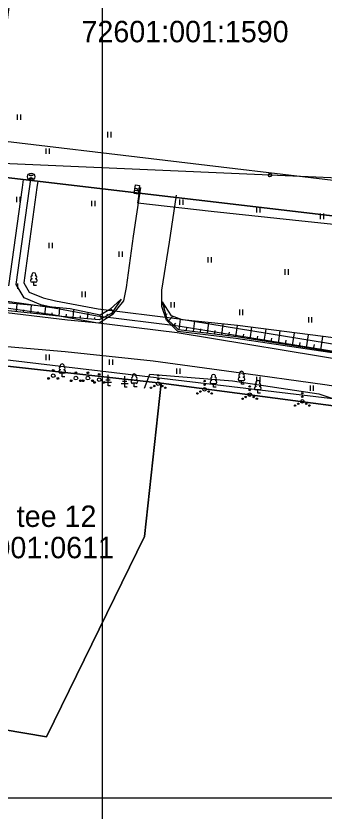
# Model space of a CAD drawing. Extents: x 532656 to 533339, y 6581345 to 6581629.
# Drawn here: x 533015 to 533058.1, y 6581419.8 to 6581531.1 of the extents above; entities that cross this region are included whole.
import ezdxf

# ---------------------------------------------------------------- set-up
doc = ezdxf.new("R2010")
doc.units = 0
for name, color, linetype in [('ELRAJATISMP', 7, 'Continuous'), ('HALJASTUS', 7, 'Continuous'), ('KASUTUSALA', 7, 'Continuous'), ('MPKAABEL', 7, 'Continuous'), ('MPOHULIIN', 7, 'Continuous'), ('PIIR', 7, 'Continuous'), ('POST', 7, 'Continuous'), ('PR_SIDE', 7, 'Continuous'), ('PUU', 7, 'Continuous'), ('RELJEEF', 7, 'Continuous'), ('TEE', 7, 'Continuous'), ('VORMISTUS', 7, 'Continuous'), ('VORMISTUS_1', 7, 'Continuous')]:
    doc.layers.add(name, color=color, linetype=linetype)

msp = doc.modelspace()

# ---------------------------------------------------------------- linework, layer by layer
at = {"layer": 'ELRAJATISMP'}
for p, q in [((533031.58, 6581506.72), (533032.17, 6581506.62)), ((533031.62, 6581506.99), (533032.21, 6581506.89))]:
    msp.add_line(p, q, dxfattribs=at)
msp.add_lwpolyline([(533031.51, 6581506.26), (533031.7, 6581507.44), (533032.29, 6581507.34), (533032.09, 6581506.17)], close=True, dxfattribs=at)
at = {"layer": 'HALJASTUS'}
for p, q in [((533015.17, 6581517.3), (533015.17, 6581516.54)), ((533015.63, 6581517.3), (533015.63, 6581516.54)), ((533027.79, 6581514.85), (533027.79, 6581514.09)), ((533028.24, 6581514.85), (533028.24, 6581514.09)), ((533019.18, 6581512.53), (533019.18, 6581511.77)), ((533019.64, 6581512.53), (533019.64, 6581511.77)), ((533015.05, 6581505.77), (533015.05, 6581505.01)), ((533015.5, 6581505.77), (533015.5, 6581505.01)), ((533025.55, 6581505.22), (533025.55, 6581504.46)), ((533026.01, 6581505.22), (533026.01, 6581504.46)), ((533037.89, 6581505.42), (533037.89, 6581504.66)), ((533038.35, 6581505.42), (533038.35, 6581504.66)), ((533048.65, 6581504.32), (533048.65, 6581503.56)), ((533049.11, 6581504.32), (533049.11, 6581503.56)), ((533057.56, 6581503.44), (533057.56, 6581502.67)), ((533058.01, 6581503.44), (533058.01, 6581502.67)), ((533019.6, 6581499.35), (533019.6, 6581498.59)), ((533020.06, 6581499.35), (533020.06, 6581498.59)), ((533029.39, 6581498.13), (533029.39, 6581497.37)), ((533029.85, 6581498.13), (533029.85, 6581497.37)), ((533041.86, 6581497.33), (533041.86, 6581496.57)), ((533042.31, 6581497.33), (533042.31, 6581496.57)), ((533052.64, 6581495.63), (533052.64, 6581494.87)), ((533053.1, 6581495.63), (533053.1, 6581494.87)), ((533015.21, 6581493.65), (533015.21, 6581492.89)), ((533024.2, 6581492.51), (533024.2, 6581491.75)), ((533024.66, 6581492.51), (533024.66, 6581491.75)), ((533036.67, 6581491.04), (533036.67, 6581490.28)), ((533037.12, 6581491.04), (533037.12, 6581490.28)), ((533046.25, 6581489.99), (533046.25, 6581489.23)), ((533046.7, 6581489.99), (533046.7, 6581489.23)), ((533055.91, 6581488.93), (533055.91, 6581488.17)), ((533056.37, 6581488.93), (533056.37, 6581488.17)), ((533019.18, 6581483.69), (533019.18, 6581482.93)), ((533019.63, 6581483.69), (533019.63, 6581482.93)), ((533028.04, 6581483.02), (533028.04, 6581482.25)), ((533028.49, 6581483.02), (533028.49, 6581482.25)), ((533037.45, 6581481.75), (533037.45, 6581480.99)), ((533037.9, 6581481.75), (533037.9, 6581480.99)), ((533048.64, 6581480.6), (533048.64, 6581479.84)), ((533049.1, 6581480.6), (533049.1, 6581479.84)), ((533056.15, 6581479.38), (533056.15, 6581478.62)), ((533056.6, 6581479.38), (533056.6, 6581478.62))]:
    msp.add_line(p, q, dxfattribs=at)
msp.add_lwpolyline([(533032.97, 6581478.99), (533033.72, 6581480.95), (533045.3, 6581480.01), (533057.4, 6581478.22), (533063.59, 6581476.17), (533064.85, 6581474.81)], dxfattribs=at)
for centre, radius in [((533034.89, 6581480.78), 0.1), ((533034.89, 6581480.28), 0.1), ((533041.38, 6581479.99), 0.1), ((533033.89, 6581479.05), 0.1), ((533034.33, 6581479.3), 0.1), ((533034.89, 6581479.63), 0.25), ((533035.46, 6581479.3), 0.1), ((533035.89, 6581479.05), 0.1), ((533041.38, 6581478.84), 0.25), ((533041.38, 6581479.49), 0.1), ((533047.7, 6581479.25), 0.1), ((533047.7, 6581478.75), 0.1), ((533040.38, 6581478.27), 0.1), ((533040.81, 6581478.52), 0.1), ((533041.94, 6581478.52), 0.1), ((533042.38, 6581478.27), 0.1), ((533047.14, 6581477.77), 0.1), ((533047.7, 6581478.1), 0.25), ((533048.27, 6581477.77), 0.1), ((533055.06, 6581478.3), 0.1), ((533055.06, 6581477.8), 0.1), ((533046.7, 6581477.52), 0.1), ((533048.7, 6581477.52), 0.1), ((533054.06, 6581476.57), 0.1), ((533054.49, 6581476.82), 0.1), ((533055.06, 6581477.15), 0.25), ((533055.62, 6581476.82), 0.1), ((533056.06, 6581476.57), 0.1)]:
    msp.add_circle(centre, radius, dxfattribs=at)
at = {"layer": 'KASUTUSALA'}
for points in [[(533013.98, 6581493.3), (533015.9, 6581507.09), (533016.05, 6581508.19), (533018.04, 6581507.96), (533017.92, 6581507.09), (533016.06, 6581493.72), (533016.82, 6581492.43), (533018.77, 6581491.63), (533020.53, 6581491.21), (533026.48, 6581490.1), (533037.85, 6581488.72), (533062.74, 6581484.63), (533088.6, 6581481.18), (533109.16, 6581472.91), (533120.73, 6581472.5), (533130.59, 6581473.14), (533152.46, 6581478.24)], [(533152.98, 6581476.31), (533130.88, 6581471.16), (533119.05, 6581470.39), (533116.99, 6581470.63), (533106.31, 6581471.91), (533088.09, 6581479.24), (533062.44, 6581482.66), (533037.57, 6581486.74), (533026.18, 6581488.12), (533021.07, 6581489.07), (533020.13, 6581489.24), (533009.66, 6581490.74)]]:
    msp.add_lwpolyline(points, dxfattribs=at)
at = {"layer": 'MPKAABEL'}
msp.add_lwpolyline([(533187.88, 6581502.84), (533186.34, 6581502.82), (533179.65, 6581502.93), (533170.99, 6581502.81), (533161.86, 6581502.74), (533157.45, 6581501.85), (533146.33, 6581499.15), (533143.65, 6581498.48), (533132.32, 6581495.71), (533125.95, 6581494.5), (533114.52, 6581495.45), (533102.79, 6581496.92), (533089.47, 6581498.82), (533077.24, 6581500), (533065.63, 6581501.23), (533053.69, 6581502.51), (533042.29, 6581503.73), (533032.02, 6581504.88), (533032.28, 6581506.42), (533031.89, 6581506.81)], dxfattribs=at)
msp.add_lwpolyline([(533187.88, 6581502.84), (533186.34, 6581502.82), (533179.65, 6581502.93), (533170.99, 6581502.81), (533161.86, 6581502.74), (533157.45, 6581501.85), (533146.33, 6581499.15), (533143.65, 6581498.48), (533132.32, 6581495.71), (533125.95, 6581494.5), (533114.52, 6581495.45), (533102.79, 6581496.92), (533089.47, 6581498.82), (533077.24, 6581500), (533065.63, 6581501.23), (533053.69, 6581502.51), (533042.29, 6581503.73), (533032.02, 6581504.88), (533032.28, 6581506.42), (533031.89, 6581506.81)], dxfattribs=at)
at = {"layer": 'MPOHULIIN'}
msp.add_lwpolyline([(533275.32, 6581502.37), (533268.53, 6581499.28), (533228.29, 6581500.87), (533187.88, 6581502.84), (533141.43, 6581504.88), (533095.45, 6581506.85), (533050.54, 6581508.81), (533010.87, 6581510.54), (532997.7, 6581528.31)], dxfattribs=at)
at = {"layer": 'PIIR'}
for points in [[(532997.7, 6581558.35), (533016.96, 6581555.16), (533011.51, 6581513.79), (533060.19, 6581508.02), (533066.33, 6581546.98), (533091.13, 6581542.87), (533143.65, 6581562.67), (533173.8, 6581529.09), (533205.25, 6581513.98), (533125.12, 6581495.35), (532997.7, 6581510.35)], [(532997.7, 6581510.35), (533125.12, 6581495.35), (533271.76, 6581529.44), (533289.68, 6581507.68), (533127.07, 6581468.59), (533126.77, 6581469.47), (532997.7, 6581484.84)], [(532997.7, 6581483.86), (533035.33, 6581479.69), (533123.26, 6581468.15), (533127.07, 6581468.59), (533126.77, 6581469.47), (532997.7, 6581484.84)], [(532997.7, 6581433.84), (533019.26, 6581430.2), (533032.98, 6581458.23), (533035.33, 6581479.69), (532997.7, 6581483.86)], [(533141.13, 6581421.68), (533127.07, 6581468.59), (533123.26, 6581468.15), (533035.33, 6581479.69), (533032.98, 6581458.23), (533019.26, 6581430.2), (532997.7, 6581433.84)]]:
    msp.add_lwpolyline(points, dxfattribs=at)
msp.add_lwpolyline([(533066.33, 6581546.98), (533016.96, 6581555.16), (533011.51, 6581513.79), (533060.19, 6581508.02)], close=True, dxfattribs=at)
at = {"layer": 'POST'}
for radius in [0.25, 0.0234]:
    msp.add_circle((533050.54, 6581508.81), radius, dxfattribs=at)
at = {"layer": 'PR_SIDE'}
for p, q in [((533016.82, 6581508.79), (533017.4, 6581508.79)), ((533016.82, 6581508.39), (533017.4, 6581508.39))]:
    msp.add_line(p, q, dxfattribs=at)
for points in [[(533009.76, 6581491.73), (533020.32, 6581490.23), (533026.33, 6581489.11), (533037.71, 6581487.73), (533062.59, 6581483.65), (533088.35, 6581480.21), (533108.95, 6581471.92), (533120.75, 6581471.5), (533130.73, 6581472.15), (533152.72, 6581477.27), (533179.95, 6581485.59), (533320.87, 6581524.82)], [(533020.32, 6581490.23), (533018.47, 6581490.68), (533016.13, 6581491.63), (533015.02, 6581493.51), (533017.11, 6581508.59)]]:
    msp.add_lwpolyline(points, dxfattribs=at)
msp.add_circle((533017.11, 6581508.59), 0.5, dxfattribs=at)
at = {"layer": 'PUU'}
for p, q in [((533017.72, 6581493.83), (533017.24, 6581493.83)), ((533017.48, 6581493.35), (533017.48, 6581493.83)), ((533017.86, 6581493.35), (533017.48, 6581493.35)), ((533021.69, 6581481.08), (533021.21, 6581481.08)), ((533021.45, 6581480.6), (533021.45, 6581481.08)), ((533021.83, 6581480.6), (533021.45, 6581480.6)), ((533028.17, 6581480.11), (533027.57, 6581480.11)), ((533028.02, 6581480.41), (533027.72, 6581480.41)), ((533027.87, 6581479.31), (533027.87, 6581480.88)), ((533030.5, 6581479.92), (533029.9, 6581479.92)), ((533030.35, 6581480.22), (533030.05, 6581480.22)), ((533030.2, 6581479.12), (533030.2, 6581480.69)), ((533046.8, 6581480.04), (533046.32, 6581480.04)), ((533046.56, 6581479.57), (533046.56, 6581480.04)), ((533028.37, 6581479.81), (533027.37, 6581479.81)), ((533028.23, 6581479.31), (533027.87, 6581479.31)), ((533030.7, 6581479.62), (533029.7, 6581479.62)), ((533030.56, 6581479.12), (533030.2, 6581479.12)), ((533031.79, 6581479.68), (533031.31, 6581479.68)), ((533031.55, 6581479.2), (533031.55, 6581479.68)), ((533031.93, 6581479.2), (533031.55, 6581479.2)), ((533042.88, 6581479.61), (533042.4, 6581479.61)), ((533042.64, 6581479.13), (533042.64, 6581479.61)), ((533043.02, 6581479.13), (533042.64, 6581479.13)), ((533046.94, 6581479.57), (533046.56, 6581479.57)), ((533049.09, 6581478.76), (533048.61, 6581478.76)), ((533048.85, 6581478.28), (533048.85, 6581478.76)), ((533049.23, 6581478.28), (533048.85, 6581478.28))]:
    msp.add_line(p, q, dxfattribs=at)
for centre, radius in [((533020.2, 6581481.49), 0.125), ((533023.37, 6581481.16), 0.125), ((533025.05, 6581481.16), 0.125), ((533026.64, 6581480.94), 0.125), ((533019.55, 6581480.37), 0.125), ((533020.2, 6581480.74), 0.25), ((533020.85, 6581480.37), 0.125), ((533022.72, 6581480.04), 0.125), ((533023.37, 6581480.41), 0.25), ((533024.02, 6581480.04), 0.125), ((533024.4, 6581480.04), 0.125), ((533025.05, 6581480.41), 0.25), ((533025.7, 6581480.04), 0.125), ((533025.99, 6581479.81), 0.125), ((533026.64, 6581480.19), 0.25), ((533027.29, 6581479.81), 0.125)]:
    msp.add_circle(centre, radius, dxfattribs=at)
for centre, radius, start, end in [((533017.31, 6581494.52), 0.233, 109.0217, 253.1415), ((533017.48, 6581494.87), 0.277, 332.5799, 207.4201), ((533017.65, 6581494.52), 0.233, 286.8508, 70.9859), ((533017.25, 6581494.06), 0.238, 90.0016, 269.3953), ((533017.72, 6581494.06), 0.238, 270.6047, 89.9984), ((533021.45, 6581482.12), 0.277, 332.5799, 207.4201), ((533021.21, 6581481.32), 0.238, 90.0016, 269.3953), ((533021.28, 6581481.78), 0.233, 109.0217, 253.1415), ((533021.62, 6581481.78), 0.233, 286.8508, 70.9859), ((533021.68, 6581481.32), 0.238, 270.6047, 89.9984), ((533046.56, 6581481.09), 0.277, 332.5799, 207.4201), ((533031.31, 6581479.91), 0.238, 90.0016, 269.3953), ((533031.38, 6581480.37), 0.233, 109.0217, 253.1415), ((533031.55, 6581480.72), 0.277, 332.5799, 207.4201), ((533031.72, 6581480.37), 0.233, 286.8508, 70.9859), ((533031.79, 6581479.91), 0.238, 270.6047, 89.9984), ((533042.4, 6581479.85), 0.238, 90.0016, 269.3953), ((533042.47, 6581480.31), 0.233, 109.0217, 253.1415), ((533042.64, 6581480.65), 0.277, 332.5799, 207.4201), ((533042.81, 6581480.31), 0.233, 286.8508, 70.9859), ((533042.88, 6581479.85), 0.238, 270.6047, 89.9984), ((533046.32, 6581480.28), 0.238, 90.0016, 269.3953), ((533046.39, 6581480.74), 0.233, 109.0217, 253.1415), ((533046.73, 6581480.74), 0.233, 286.8508, 70.9859), ((533046.8, 6581480.28), 0.238, 270.6047, 89.9984), ((533048.85, 6581479.8), 0.277, 332.5799, 207.4201), ((533048.61, 6581478.99), 0.238, 90.0016, 269.3953), ((533048.68, 6581479.45), 0.233, 109.0217, 253.1415), ((533049.02, 6581479.45), 0.233, 286.8508, 70.9859), ((533049.09, 6581478.99), 0.238, 270.6047, 89.9984)]:
    msp.add_arc(centre, radius, start, end, dxfattribs=at)
at = {"layer": 'RELJEEF'}
for p, q in [((533015.05, 6581489.69), (533015.17, 6581490.78)), ((533016.05, 6581489.58), (533016.09, 6581489.95)), ((533017.04, 6581489.48), (533017.16, 6581490.6)), ((533019.03, 6581489.27), (533019.15, 6581490.41)), ((533021.02, 6581489.06), (533021.14, 6581490.23)), ((533023.01, 6581488.86), (533023.1, 6581489.98)), ((533028.6, 6581489.79), (533028.18, 6581490.08)), ((533029.16, 6581490.62), (533029.09, 6581490.67)), ((533035.71, 6581490.32), (533035.94, 6581490.39)), ((533018.04, 6581489.37), (533018.08, 6581489.75)), ((533020.02, 6581489.16), (533020.07, 6581489.55)), ((533022.01, 6581488.95), (533022.06, 6581489.35)), ((533024.01, 6581488.78), (533024.03, 6581489.11)), ((533025, 6581488.7), (533025.07, 6581489.57)), ((533026, 6581488.62), (533026.02, 6581488.87)), ((533026.96, 6581488.73), (533026.71, 6581489.23)), ((533027.85, 6581489.18), (533027.76, 6581489.36)), ((533035.98, 6581489.36), (533036.15, 6581489.41)), ((533036.36, 6581488.47), (533036.9, 6581489.05)), ((533037.09, 6581487.78), (533037.37, 6581488.08)), ((533037.84, 6581487.15), (533038.03, 6581488.65)), ((533039.83, 6581486.91), (533040.01, 6581488.4)), ((533041.81, 6581486.67), (533042, 6581488.2)), ((533043.8, 6581486.43), (533043.99, 6581487.99)), ((533045.78, 6581486.18), (533045.98, 6581487.79)), ((533038.84, 6581487.03), (533038.9, 6581487.52)), ((533040.82, 6581486.79), (533040.88, 6581487.29)), ((533042.81, 6581486.55), (533042.87, 6581487.06)), ((533044.79, 6581486.31), (533044.86, 6581486.83)), ((533047.76, 6581485.88), (533048.02, 6581487.53)), ((533049.74, 6581485.57), (533050, 6581487.27)), ((533051.71, 6581485.26), (533051.98, 6581487)), ((533053.69, 6581484.95), (533053.97, 6581486.74)), ((533046.77, 6581486.03), (533046.86, 6581486.57)), ((533048.75, 6581485.72), (533048.84, 6581486.28)), ((533050.72, 6581485.42), (533050.81, 6581485.99)), ((533052.7, 6581485.11), (533052.79, 6581485.7)), ((533055.67, 6581484.65), (533055.95, 6581486.48)), ((533057.64, 6581484.34), (533057.93, 6581486.22)), ((533054.68, 6581484.8), (533054.77, 6581485.41)), ((533056.65, 6581484.49), (533056.75, 6581485.11))]:
    msp.add_line(p, q, dxfattribs=at)
for points in [[(533281.18, 6581520.42), (533276.05, 6581519.36), (533263.6, 6581516.53), (533251.65, 6581514.59), (533239.04, 6581512.21), (533226.47, 6581508.91), (533214.68, 6581505.26), (533201.89, 6581501.28), (533176.76, 6581494.49), (533164.99, 6581490.87), (533152.25, 6581486.88), (533140.46, 6581483.59), (533129.53, 6581479.74), (533118.62, 6581478.85), (533106.28, 6581479.43), (533097.7, 6581480.38), (533085.54, 6581482.56), (533072.44, 6581484.31), (533059.43, 6581486.03), (533046.01, 6581487.79), (533038.24, 6581488.57), (533036.77, 6581489.1), (533035.51, 6581491.06)], [(533281.56, 6581519.42), (533276.26, 6581518.13), (533263.82, 6581515.5), (533251.69, 6581513.67), (533239.15, 6581511.33), (533226.72, 6581507.82), (533214.83, 6581504.27), (533202.1, 6581500.22), (533189.78, 6581497.01), (533177.29, 6581493.01), (533165.35, 6581489.17), (533152.46, 6581485.11), (533140.73, 6581481.56), (533129.52, 6581478.53), (533118.47, 6581477.73), (533106, 6581477.89), (533097.29, 6581479.13), (533084.98, 6581481.19), (533071.98, 6581482.38), (533058.89, 6581484.14), (533045.84, 6581486.18), (533037.75, 6581487.16), (533036.17, 6581488.64), (533035.51, 6581491.06)], [(533029.72, 6581491.45), (533028.35, 6581489.43), (533026.64, 6581488.57), (533022.29, 6581488.92), (533011.25, 6581490.09), (533007.24, 6581491.27)], [(533029.72, 6581491.45), (533028.12, 6581490.03), (533026.75, 6581489.22), (533022.55, 6581490.09), (533011.44, 6581491.13), (533007.24, 6581491.27)]]:
    msp.add_lwpolyline(points, dxfattribs=at)
at = {"layer": 'TEE'}
for points in [[(533032.43, 6581507.08), (533031.38, 6581500.28), (533030.42, 6581493.08), (533030.02, 6581491.2), (533028.43, 6581489.24), (533026.62, 6581488.1), (533022.18, 6581488.52), (533011.27, 6581489.84), (533006.27, 6581490.83), (533003.24, 6581492.66), (533000.62, 6581495.23), (532998.67, 6581499.37), (532997.7, 6581502)], [(533140.89, 6581480.63), (533129.55, 6581478.32), (533118.51, 6581477.4), (533105.92, 6581477.64), (533096.99, 6581478.44), (533084.67, 6581480.03), (533071.89, 6581482.05), (533058.9, 6581483.97), (533045.77, 6581485.95), (533037.63, 6581486.92), (533036.04, 6581488.52), (533035.42, 6581490.45), (533035.42, 6581492.71), (533036.48, 6581499.41), (533037.46, 6581506.01)], [(533011.56, 6581485.02), (533021.87, 6581484.15), (533034.21, 6581482.84), (533045.47, 6581481.3), (533058.22, 6581479.5), (533071.17, 6581477.55), (533083.74, 6581475.92), (533096.64, 6581474.2), (533105.72, 6581473.21), (533110.01, 6581472.82), (533120.73, 6581472.5), (533130.59, 6581473.14), (533142.41, 6581475.8)]]:
    msp.add_lwpolyline(points, dxfattribs=at)
at = {"layer": 'VORMISTUS'}
msp.add_lwpolyline([(533309.59, 6581421.68), (533309.59, 6581605.42), (532997.7, 6581605.42), (532997.7, 6581421.68)], close=True, dxfattribs=at)
msp.add_lwpolyline([(532997.7, 6581421.68), (533309.59, 6581421.68)], dxfattribs=at)
at = {"layer": 'VORMISTUS_1'}
msp.add_lwpolyline([(532655.8, 6581607.74), (533027.05, 6581607.74), (533027.05, 6581345.24), (532655.8, 6581345.24)], close=True, dxfattribs=at)

# ---------------------------------------------------------------- texts
at = {"layer": 'PIIR'}
for s, p in [('72601:001:1590', (533024.15, 6581527.4)), ('Kaasiku tee 12', (532999.7, 6581459.58)), ('72701:001:0611', (532999.7, 6581455.2))]:
    msp.add_text(s, height=3, dxfattribs=at).set_placement(p)

doc.saveas('drawing.dxf')
